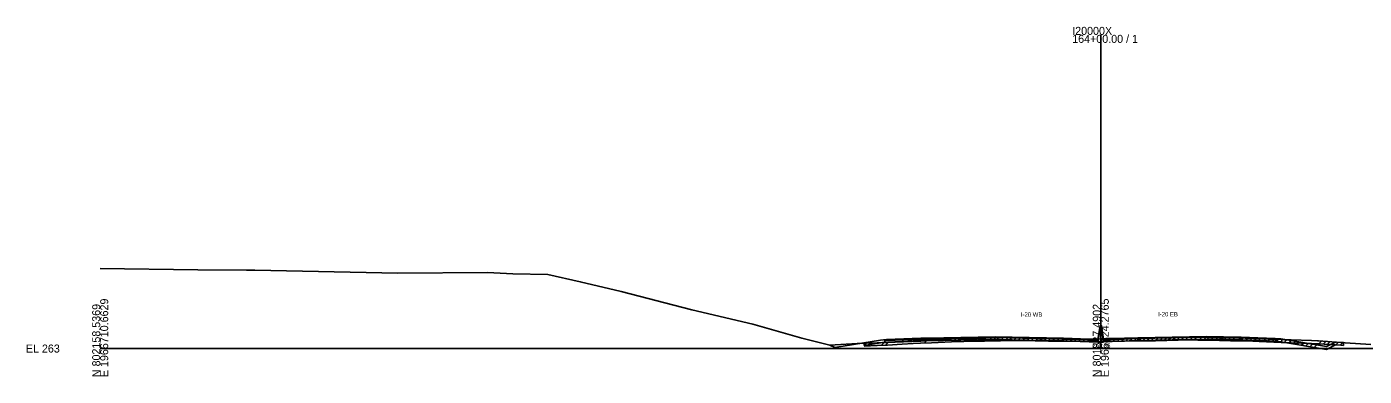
# Model space of a CAD drawing. Extents: x -4026 to 9638, y -10 to 19609.
# Drawn here: x 3974.3 to 4442.2, y 5490.3 to 5612.6 of the extents above; entities that cross this region are included whole.
import ezdxf

# ---------------------------------------------------------------- set-up
doc = ezdxf.new("R2010")
doc.units = 0
for name, color, linetype in [('Default', 7, 'Continuous'), ('RD_GPK_XS_Cell', 7, 'Continuous'), ('RD_TX_Misc1', 7, 'Continuous'), ('RD_XS_Base', 7, 'Continuous'), ('RD_XS_ExGround', 7, 'Continuous'), ('RD_XS_ExPaveRet', 7, 'Continuous'), ('RD_XS_Greenside', 7, 'Continuous'), ('RD_XS_MedBWall', 7, 'Continuous'), ('RD_XS_Pave', 7, 'Continuous'), ('RD_XS_PaveOvlay', 7, 'Continuous'), ('RD_XS_TieSlope', 7, 'Continuous'), ('RD_XS_TX_Elev_EX', 7, 'Continuous')]:
    doc.layers.add(name, color=color, linetype=linetype)

msp = doc.modelspace()

# ---------------------------------------------------------------- linework, layer by layer
at = {"layer": 'RD_GPK_XS_Cell'}
for p, q in [((4350, 5500), (4350, 5609.73)), ((4000, 5500), (4350, 5500)), ((4350, 5500), (4700, 5500))]:
    msp.add_line(p, q, dxfattribs=at)
at = {"layer": 'RD_XS_Base'}
for points in [[(4274.5, 5502.79), (4275, 5502.81), (4287, 5503.28)], [(4274.5, 5502.12), (4274.5, 5502.79)], [(4287, 5502.61), (4274.5, 5502.12)], [(4287, 5503.28), (4289, 5503.33)], [(4287, 5502.61), (4287, 5503.28)], [(4289, 5502.66), (4287, 5502.61)], [(4337, 5503.33), (4313, 5503.82), (4289, 5503.33)], [(4289, 5503.33), (4289, 5502.66)], [(4289, 5502.66), (4313, 5503.15), (4337, 5502.66)], [(4337, 5502.66), (4337, 5503.33)], [(4349, 5502.86), (4337, 5503.33)], [(4337, 5502.66), (4349, 5502.19)], [(4349, 5502.19), (4349, 5502.86)], [(4351, 5502.98), (4363, 5503.46)], [(4351, 5502.31), (4351, 5502.98)], [(4363, 5502.79), (4351, 5502.31)], [(4363, 5503.46), (4387, 5503.94), (4399, 5503.7)], [(4363, 5502.79), (4363, 5503.46)], [(4399, 5503.03), (4387, 5503.27), (4363, 5502.79)], [(4399, 5503.7), (4399, 5503.7), (4399, 5503.03), (4399, 5503.03)], [(4399, 5503.03), (4399, 5503.7)], [(4411.5, 5503.2), (4411, 5503.22), (4399, 5503.7)], [(4399, 5503.03), (4411.5, 5502.53)], [(4411.5, 5502.53), (4411.5, 5503.2)]]:
    msp.add_lwpolyline(points, dxfattribs=at)
at = {"layer": 'RD_XS_ExGround'}
msp.add_lwpolyline([(4000, 5527.96), (4034.14, 5527.59), (4051.22, 5527.36), (4054.12, 5527.38), (4104.13, 5526.31), (4135.46, 5526.55), (4144.36, 5526.15), (4156.52, 5525.92), (4167.93, 5523.34), (4182.23, 5519.97), (4206.97, 5513.59), (4228.25, 5508.58), (4245.4, 5503.64), (4255.22, 5501.17), (4264.77, 5501.71), (4267.23, 5501.86), (4271.77, 5502.05), (4275.43, 5502.22), (4280.55, 5502.52), (4284.34, 5502.73), (4286.91, 5502.87), (4290.76, 5503.05), (4297.74, 5503.38), (4306.42, 5503.56), (4308.46, 5503.61), (4309.36, 5503.63), (4320.52, 5503.86), (4327.05, 5503.73), (4331.75, 5503.63), (4336.8, 5503.53), (4342.81, 5503.43), (4346.98, 5503.33), (4348.81, 5503.29), (4350, 5503.36), (4351.37, 5503.44), (4351.86, 5503.46), (4353.2, 5503.5), (4358.24, 5503.6), (4361.33, 5503.64), (4369.16, 5503.73), (4377.04, 5503.92), (4380.8, 5504.01), (4383.99, 5503.94), (4391.56, 5503.78), (4395.32, 5503.74), (4397.72, 5503.7), (4403.2, 5503.55), (4405.42, 5503.48), (4413.07, 5503.15), (4414.27, 5503.1), (4416.61, 5503.03), (4423.72, 5502.81), (4425.79, 5502.69), (4426.19, 5502.67), (4433.93, 5502.14), (4434.87, 5502.08), (4435.46, 5502.04), (4444.45, 5501.45)], dxfattribs=at)
at = {"layer": 'RD_XS_ExPaveRet'}
for p, q in [((4349, 5502.19), (4349.75, 5506.98)), ((4349.75, 5506.98), (4350.25, 5506.98)), ((4350.25, 5506.98), (4351, 5502.31)), ((4267.23, 5501.02), (4273, 5501.98)), ((4267.23, 5501.02), (4268.1, 5501.89)), ((4268.73, 5501.27), (4269.41, 5501.95)), ((4270.23, 5501.52), (4270.72, 5502.01)), ((4271.73, 5501.77), (4272.02, 5502.07)), ((4273, 5501.98), (4275, 5502.14)), ((4273.23, 5501.12), (4274.27, 5502.17)), ((4274.73, 5501.19), (4275.78, 5502.24)), ((4275, 5502.14), (4287, 5502.62)), ((4276.23, 5502.19), (4276.31, 5502.27)), ((4277.73, 5502.25), (4277.84, 5502.36)), ((4279.23, 5502.31), (4279.37, 5502.45)), ((4280.73, 5502.37), (4280.89, 5502.54)), ((4282.23, 5502.43), (4282.42, 5502.62)), ((4283.73, 5502.49), (4283.95, 5502.71)), ((4285.23, 5502.55), (4285.47, 5502.79)), ((4286.73, 5502.61), (4286.99, 5502.88)), ((4286.91, 5501.87), (4290.76, 5502.05)), ((4287, 5502.62), (4289, 5502.67)), ((4288.23, 5501.93), (4289.27, 5502.98)), ((4289, 5502.67), (4313, 5503.15)), ((4289.73, 5502.68), (4290.06, 5503.02)), ((4290.76, 5502.05), (4297.74, 5502.38)), ((4291.23, 5502.71), (4291.6, 5503.09)), ((4292.73, 5502.74), (4293.14, 5503.16)), ((4294.23, 5502.77), (4294.69, 5503.24)), ((4295.73, 5502.8), (4296.23, 5503.31)), ((4297.23, 5502.83), (4297.77, 5503.38)), ((4297.74, 5502.38), (4306.42, 5502.56)), ((4298.73, 5502.86), (4299.27, 5503.41)), ((4300.23, 5502.89), (4300.78, 5503.44)), ((4301.73, 5502.92), (4302.28, 5503.47)), ((4303.23, 5502.95), (4303.78, 5503.51)), ((4304.73, 5502.98), (4305.28, 5503.54)), ((4306.23, 5503.01), (4306.78, 5503.57)), ((4306.42, 5502.56), (4308.46, 5502.61)), ((4307.73, 5503.04), (4308.29, 5503.6)), ((4308.46, 5502.61), (4309.36, 5502.63)), ((4309.23, 5503.07), (4309.79, 5503.63)), ((4309.36, 5502.63), (4320.52, 5502.86)), ((4310.73, 5502.65), (4311.75, 5503.68)), ((4312.23, 5502.69), (4313.25, 5503.71)), ((4313, 5503.15), (4337, 5502.67)), ((4313.73, 5503.14), (4314.32, 5503.73)), ((4315.23, 5503.11), (4315.89, 5503.77)), ((4316.73, 5503.08), (4317.45, 5503.8)), ((4318.23, 5503.05), (4319.01, 5503.83)), ((4319.73, 5503.02), (4320.57, 5503.86)), ((4320.52, 5502.86), (4327.05, 5502.73)), ((4321.23, 5502.99), (4322.07, 5503.83)), ((4322.73, 5502.96), (4323.57, 5503.8)), ((4324.23, 5502.93), (4325.07, 5503.77)), ((4325.73, 5502.9), (4326.57, 5503.74)), ((4327.05, 5502.73), (4331.75, 5502.63)), ((4327.23, 5502.87), (4328.07, 5503.7)), ((4328.73, 5502.84), (4329.56, 5503.67)), ((4330.23, 5502.81), (4331.06, 5503.64)), ((4331.73, 5502.78), (4332.56, 5503.61)), ((4331.75, 5502.63), (4336.8, 5502.53)), ((4333.23, 5502.75), (4334.06, 5503.58)), ((4334.73, 5502.72), (4335.57, 5503.55)), ((4336.23, 5502.69), (4337.07, 5503.53)), ((4336.8, 5502.53), (4342.81, 5502.43)), ((4337, 5502.67), (4349, 5502.19)), ((4337.73, 5502.64), (4338.59, 5503.5)), ((4339.23, 5502.58), (4340.12, 5503.48)), ((4340.73, 5502.52), (4341.66, 5503.45)), ((4342.23, 5502.46), (4343.19, 5503.42)), ((4342.81, 5502.43), (4346.98, 5502.33)), ((4343.73, 5502.4), (4344.69, 5503.36)), ((4345.23, 5502.34), (4346.19, 5503.3)), ((4346.73, 5502.28), (4347.69, 5503.24)), ((4346.98, 5502.33), (4348.81, 5502.29)), ((4348.23, 5502.22), (4349.32, 5503.32)), ((4348.81, 5502.29), (4350, 5502.36)), ((4349.73, 5502.34), (4350.79, 5503.41)), ((4350, 5502.36), (4351.37, 5502.44)), ((4351, 5502.31), (4363, 5502.79)), ((4351.23, 5502.32), (4352.27, 5503.36)), ((4351.37, 5502.44), (4351.86, 5502.46)), ((4351.86, 5502.46), (4353.2, 5502.5)), ((4352.73, 5502.38), (4353.77, 5503.42)), ((4353.2, 5502.5), (4358.24, 5502.6)), ((4354.23, 5502.44), (4355.27, 5503.48)), ((4355.73, 5502.5), (4356.77, 5503.54)), ((4357.23, 5502.56), (4358.26, 5503.6)), ((4358.24, 5502.6), (4361.33, 5502.64)), ((4358.73, 5502.62), (4359.72, 5503.62)), ((4360.23, 5502.68), (4361.19, 5503.64)), ((4361.33, 5502.64), (4369.16, 5502.73)), ((4361.73, 5502.65), (4362.74, 5503.66)), ((4363, 5502.79), (4387, 5503.27)), ((4363.23, 5502.8), (4364.1, 5503.67)), ((4364.73, 5502.83), (4365.59, 5503.69)), ((4366.23, 5502.86), (4367.08, 5503.71)), ((4367.73, 5502.89), (4368.57, 5503.73)), ((4369.16, 5502.73), (4377.04, 5502.92)), ((4369.23, 5502.92), (4370.07, 5503.76)), ((4370.73, 5502.95), (4371.57, 5503.79)), ((4372.23, 5502.98), (4373.08, 5503.83)), ((4373.73, 5503.01), (4374.58, 5503.86)), ((4375.23, 5503.04), (4376.09, 5503.9)), ((4376.73, 5503.07), (4377.59, 5503.93)), ((4377.04, 5502.92), (4380.8, 5503.01)), ((4378.23, 5503.1), (4379.1, 5503.97)), ((4379.73, 5503.13), (4380.6, 5504)), ((4380.8, 5503.01), (4383.99, 5502.94)), ((4381.23, 5503.16), (4382.05, 5503.98)), ((4382.73, 5503.19), (4383.49, 5503.95)), ((4383.99, 5502.94), (4391.56, 5502.78)), ((4384.23, 5502.94), (4385.21, 5503.92)), ((4385.73, 5502.91), (4386.71, 5503.89)), ((4387, 5503.27), (4399, 5503.03)), ((4387.23, 5503.27), (4387.82, 5503.86)), ((4388.73, 5503.24), (4389.32, 5503.83)), ((4390.23, 5503.21), (4390.82, 5503.8)), ((4391.56, 5502.78), (4395.32, 5502.74)), ((4391.73, 5503.18), (4392.32, 5503.77)), ((4393.23, 5503.15), (4393.83, 5503.75)), ((4394.73, 5503.12), (4395.34, 5503.73)), ((4395.32, 5502.74), (4397.72, 5502.7)), ((4396.23, 5503.09), (4396.85, 5503.72)), ((4397.72, 5502.7), (4403.2, 5502.55)), ((4397.73, 5502.7), (4398.7, 5503.68)), ((4399, 5503.03), (4411, 5502.55)), ((4399.23, 5503.02), (4399.85, 5503.65)), ((4400.73, 5502.96), (4401.37, 5503.6)), ((4402.23, 5502.9), (4402.88, 5503.56)), ((4403.2, 5502.55), (4405.42, 5502.48)), ((4403.73, 5502.84), (4404.4, 5503.52)), ((4405.23, 5502.78), (4405.91, 5503.46)), ((4405.42, 5502.48), (4413.07, 5502.15)), ((4406.73, 5502.43), (4407.68, 5503.39)), ((4408.23, 5502.36), (4409.18, 5503.32)), ((4409.73, 5502.3), (4410.68, 5503.25)), ((4411, 5502.55), (4413, 5502.39)), ((4411.23, 5502.23), (4412.18, 5503.19)), ((4412.73, 5502.16), (4413.69, 5503.12)), ((4413, 5502.39), (4429, 5499.72)), ((4413.07, 5502.15), (4414.27, 5502.1)), ((4414.23, 5502.18), (4415.08, 5503.04)), ((4414.27, 5502.1), (4416.61, 5502.03)), ((4415.73, 5501.93), (4416.58, 5502.79)), ((4416.61, 5502.03), (4423.72, 5501.81)), ((4417.23, 5501.68), (4418.08, 5502.54)), ((4418.73, 5501.43), (4419.58, 5502.29)), ((4420.23, 5501.18), (4421.08, 5502.04)), ((4426.23, 5501.66), (4427.16, 5502.6)), ((4427.73, 5501.56), (4428.66, 5502.5)), ((4429.23, 5501.46), (4430.16, 5502.4)), ((4432.23, 5501.26), (4433.16, 5502.19)), ((4433.73, 5501.16), (4434.67, 5502.09)), ((4434.87, 5502.08), (4434.87, 5501.08)), ((4267.23, 5501.02), (4267.23, 5501.86)), ((4267.23, 5500.86), (4271.77, 5501.05)), ((4271.77, 5501.05), (4275.43, 5501.22)), ((4275.43, 5501.22), (4280.55, 5501.52)), ((4280.55, 5501.52), (4284.34, 5501.73)), ((4284.34, 5501.73), (4286.91, 5501.87)), ((4421.73, 5500.93), (4422.58, 5501.79)), ((4423.23, 5500.68), (4424.08, 5501.54)), ((4423.72, 5501.81), (4425.79, 5501.69)), ((4424.73, 5500.43), (4425.58, 5501.29)), ((4425.79, 5501.69), (4426.19, 5501.67)), ((4426.19, 5501.67), (4433.93, 5501.14)), ((4429, 5499.72), (4432.1, 5501.27)), ((4430.73, 5501.36), (4431.17, 5501.8)), ((4433.93, 5501.14), (4434.87, 5501.08))]:
    msp.add_line(p, q, dxfattribs=at)
at = {"layer": 'RD_XS_Greenside'}
for points in [[(4273, 5502.98), (4257, 5500.31)], [(4275, 5503.14), (4273, 5502.98)], [(4411, 5503.55), (4413, 5503.39)], [(4413, 5503.39), (4429, 5500.72)]]:
    msp.add_lwpolyline(points, dxfattribs=at)
at = {"layer": 'RD_XS_MedBWall'}
for points in [[(4349, 5503.19), (4349.75, 5507.98), (4350.25, 5507.98), (4351, 5503.31)], [(4349, 5502.19), (4349, 5503.19)], [(4351, 5502.19), (4349, 5502.19)], [(4351, 5503.31), (4351, 5502.19)]]:
    msp.add_lwpolyline(points, dxfattribs=at)
at = {"layer": 'RD_XS_Pave'}
for points in [[(4275, 5502.97), (4287, 5503.45)], [(4287, 5503.28), (4275, 5502.81)], [(4275, 5502.81), (4275, 5502.97)], [(4287, 5503.45), (4289, 5503.5)], [(4287, 5503.28), (4287, 5503.45)], [(4289, 5503.33), (4287, 5503.28)], [(4289, 5503.5), (4313, 5503.98), (4337, 5503.5)], [(4337, 5503.33), (4313, 5503.82), (4289, 5503.33)], [(4289, 5503.5), (4289, 5503.33)], [(4337, 5503.5), (4349, 5503.03)], [(4337, 5503.33), (4337, 5503.5)], [(4349, 5502.86), (4337, 5503.33)], [(4349, 5503.03), (4349, 5502.86)], [(4363, 5503.63), (4351, 5503.15)], [(4351, 5502.98), (4363, 5503.46)], [(4351, 5503.15), (4351, 5502.98)], [(4399, 5503.87), (4387, 5504.11), (4363, 5503.63)], [(4363, 5503.46), (4387, 5503.94), (4399, 5503.7)], [(4363, 5503.63), (4363, 5503.46)], [(4399, 5503.87), (4399, 5503.87), (4399, 5503.7), (4399, 5503.7)], [(4399, 5503.7), (4399, 5503.87)], [(4411, 5503.39), (4399, 5503.87)], [(4399, 5503.7), (4411, 5503.22)], [(4411, 5503.22), (4411, 5503.39)]]:
    msp.add_lwpolyline(points, dxfattribs=at)
at = {"layer": 'RD_XS_PaveOvlay'}
for points in [[(4275, 5503.14), (4287, 5503.62)], [(4287, 5503.45), (4275, 5502.97)], [(4275, 5502.97), (4275, 5503.14)], [(4289, 5503.67), (4287, 5503.62)], [(4287, 5503.62), (4287, 5503.45)], [(4287, 5503.45), (4289, 5503.5)], [(4289, 5503.67), (4313, 5504.15), (4337, 5503.67)], [(4337, 5503.5), (4313, 5503.98), (4289, 5503.5)], [(4289, 5503.5), (4289, 5503.67)], [(4337, 5503.67), (4337, 5503.5)], [(4337, 5503.67), (4349, 5503.19)], [(4349, 5503.03), (4337, 5503.5)], [(4349, 5503.19), (4349, 5503.03)], [(4363, 5503.79), (4351, 5503.31)], [(4351, 5503.15), (4363, 5503.63)], [(4351, 5503.31), (4351, 5503.15)], [(4399, 5504.03), (4387, 5504.27), (4363, 5503.79)], [(4363, 5503.63), (4387, 5504.11), (4399, 5503.87)], [(4363, 5503.79), (4363, 5503.63)], [(4399, 5503.87), (4399, 5504.03)], [(4399, 5504.03), (4399, 5504.03), (4399, 5503.87), (4399, 5503.87)], [(4399, 5504.03), (4411, 5503.55)], [(4411, 5503.39), (4399, 5503.87)], [(4411, 5503.55), (4411, 5503.39)]]:
    msp.add_lwpolyline(points, dxfattribs=at)
at = {"layer": 'RD_XS_TieSlope'}
for points in [[(4429, 5500.72), (4432.1, 5502.27)], [(4257, 5500.31), (4255.27, 5501.18)]]:
    msp.add_lwpolyline(points, dxfattribs=at)

# ---------------------------------------------------------------- texts
at = {"layer": 'Default'}
msp.add_text('-', height=0.0001, dxfattribs=at).set_placement((4000, 5500))
at = {"layer": 'RD_GPK_XS_Cell'}
for s, p in [('164+00.00 / 1', (4340, 5606.93)), ('I20000X', (4340, 5609.73)), ('EL 263', (3974, 5498.6))]:
    msp.add_text(s, height=2.8, dxfattribs=at).set_placement(p)
for s, p in [('E 1966710.6629', (4002.8, 5490)), ('E 1966824.2765', (4352.8, 5490)), ('N 802158.5369', (4000, 5490)), ('N 801827.4902', (4350, 5490))]:
    msp.add_text(s, height=2.8, rotation=90, dxfattribs=at).set_placement(p)
at = {"layer": 'RD_TX_Misc1'}
for s, p in [('I-20 WB', (4322.06, 5511.15)), ('I-20 EB', (4370.06, 5511.27))]:
    msp.add_text(s, height=1.5, dxfattribs=at).set_placement(p)
at = {"layer": 'RD_XS_TX_Elev_EX'}
msp.add_text('266.36', height=1.5, dxfattribs=at).set_placement((4347.04, 5500.36))

doc.saveas('drawing.dxf')
